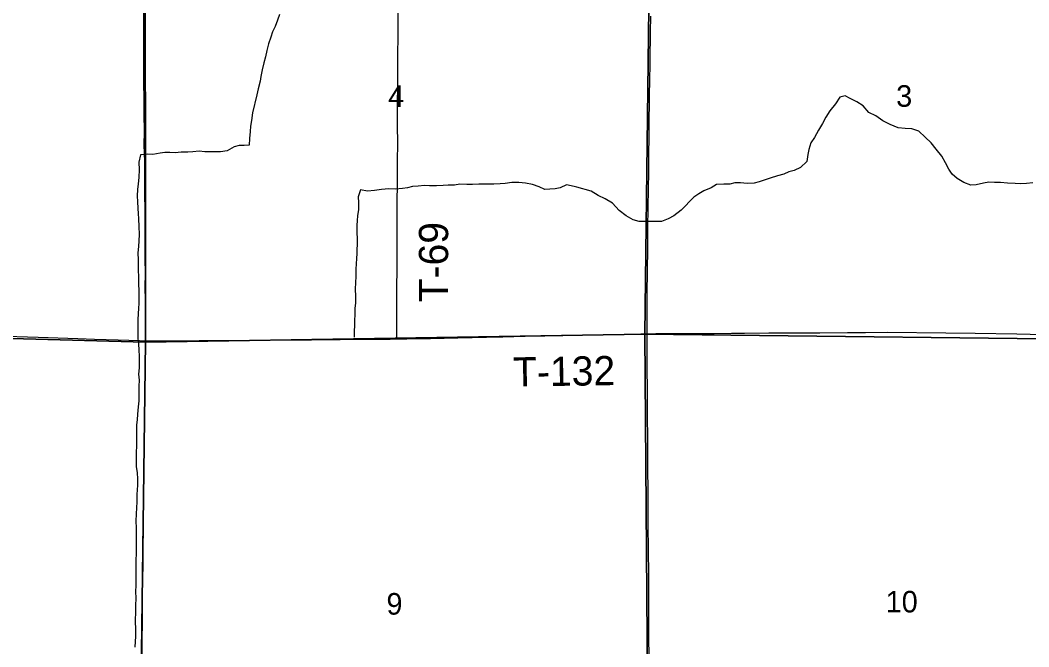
# Model space of a CAD drawing. Extents: x 0 to 34, y 0 to 22.
# Drawn here: x 3.372 to 4.352, y 19.621 to 20.23 of the extents above; entities that cross this region are included whole.
import ezdxf

# ---------------------------------------------------------------- set-up
doc = ezdxf.new("R2010")
doc.units = 0
for name, color, linetype in [('GM_X_Minor_River', 7, 'Continuous'), ('GM_X_Section', 7, 'Continuous'), ('GM_X_Section_Text', 7, 'Continuous'), ('GM_X_Township_Road', 7, 'Continuous'), ('GM_X_Township_Road_Text', 7, 'Continuous')]:
    doc.layers.add(name, color=color, linetype=linetype)

msp = doc.modelspace()

# ---------------------------------------------------------------- linework, layer by layer
at = {"layer": 'GM_X_Minor_River'}
for points in [[(3.62379, 20.23523), (3.62188, 20.22974), (3.61957, 20.22349), (3.61709, 20.21838), (3.61555, 20.21326), (3.61325, 20.20682), (3.61171, 20.20038), (3.61035, 20.19432), (3.60881, 20.18845), (3.60689, 20.18163), (3.60591, 20.17518), (3.60514, 20.17044), (3.60302, 20.16324), (3.60186, 20.15737), (3.5978, 20.13975), (3.59664, 20.13235), (3.59585, 20.12667), (3.59526, 20.12155), (3.59466, 20.11472), (3.59445, 20.10846), (3.58952, 20.10792), (3.58478, 20.10794), (3.57985, 20.10683), (3.5732, 20.10287), (3.56657, 20.10196), (3.56069, 20.10198), (3.55595, 20.10182), (3.55122, 20.10184), (3.54591, 20.10243), (3.53966, 20.1019), (3.53492, 20.10154), (3.52829, 20.10157), (3.5226, 20.10084)], [(4.35571, 20.07189), (4.34965, 20.07097), (4.34378, 20.07082), (4.33866, 20.07104), (4.33109, 20.07146), (4.32428, 20.07207), (4.3184, 20.07211), (4.3131, 20.07233), (4.30779, 20.0716), (4.30078, 20.06993), (4.29566, 20.06958), (4.28886, 20.07209), (4.28225, 20.07611), (4.27736, 20.08032), (4.27398, 20.08508), (4.27079, 20.09118), (4.26723, 20.09765), (4.26197, 20.10433), (4.2569, 20.11062), (4.25125, 20.11616), (4.24504, 20.12189), (4.23804, 20.12421), (4.23161, 20.12463), (4.22498, 20.12505), (4.21723, 20.12851), (4.20987, 20.13197), (4.20308, 20.13676), (4.19628, 20.14021), (4.19083, 20.14651), (4.18479, 20.15034), (4.17837, 20.15361), (4.17347, 20.15629), (4.16816, 20.15499), (4.16414, 20.14856), (4.15841, 20.14176), (4.15459, 20.13552), (4.15152, 20.12927), (4.1475, 20.12284), (4.14348, 20.11584), (4.14004, 20.11074), (4.13811, 20.10429), (4.13732, 20.09917), (4.13633, 20.09253), (4.13004, 20.0865), (4.12396, 20.08387), (4.11884, 20.08238), (4.11371, 20.08033), (4.10764, 20.07865), (4.10062, 20.07642), (4.09474, 20.07436), (4.08999, 20.07268), (4.08487, 20.07138), (4.07824, 20.07123), (4.07161, 20.07184), (4.06631, 20.07187), (4.06138, 20.07038), (4.05551, 20.07061), (4.04831, 20.07027), (4.04317, 20.06688), (4.03615, 20.06388), (4.03121, 20.06106), (4.02626, 20.05768), (4.01406, 20.04522), (4.00702, 20.03975), (4.00132, 20.03675), (3.99486, 20.03432), (3.98937, 20.03416), (3.97895, 20.03422), (3.97327, 20.03407), (3.9676, 20.03581), (3.96062, 20.03984), (3.95383, 20.045), (3.94724, 20.05187), (3.94026, 20.05609), (3.93346, 20.05936), (3.92667, 20.06357), (3.91275, 20.06749)], [(3.5226, 20.10084), (3.51749, 20.10124), (3.51256, 20.10108), (3.50782, 20.10072), (3.5008, 20.09923), (3.49531, 20.09964), (3.48887, 20.0991), (3.48732, 20.09171), (3.48767, 20.08431), (3.48726, 20.0773), (3.48647, 20.07047), (3.48607, 20.06573), (3.48566, 20.0589), (3.48602, 20.05378), (3.48637, 20.04676), (3.48673, 20.04201), (3.48689, 20.0367), (3.48724, 20.0293), (3.4874, 20.02171), (3.48718, 20.01526), (3.48678, 20.00976), (3.48637, 20.0037), (3.48653, 19.99687), (3.4867, 19.99174), (3.48668, 19.98681), (3.48684, 19.98036), (3.48681, 19.97372), (3.48716, 19.9667), (3.48733, 19.96196), (3.4873, 19.95494), (3.4869, 19.94963), (3.4865, 19.94489), (3.48629, 19.93882), (3.48626, 19.93294), (3.48621, 19.92042), (3.48675, 19.91549), (3.48711, 19.90922), (3.48765, 19.90353), (3.48763, 19.89822), (3.48741, 19.89215), (3.48701, 19.88589), (3.48755, 19.88001), (3.48734, 19.87413), (3.4873, 19.86465), (3.48709, 19.8599), (3.48668, 19.85403), (3.48589, 19.84701), (3.48568, 19.84151), (3.48509, 19.83677), (3.48487, 19.82861), (3.48503, 19.8216), (3.48501, 19.81647), (3.4846, 19.80946), (3.48457, 19.80358), (3.48473, 19.7958), (3.48546, 19.79048), (3.486, 19.78403), (3.48598, 19.77796), (3.48518, 19.76886), (3.48515, 19.76203), (3.48493, 19.75558), (3.48472, 19.75046), (3.48431, 19.74268), (3.48448, 19.73699), (3.48423, 19.68008), (3.48402, 19.67534), (3.48418, 19.66775), (3.48415, 19.66169), (3.48412, 19.65448), (3.48371, 19.64708), (3.48405, 19.63646), (3.48383, 19.63096), (3.48362, 19.62621), (3.48322, 19.62052)], [(3.91275, 20.06749), (3.91015, 20.06826), (3.90276, 20.06981), (3.8965, 20.067), (3.89176, 20.06607), (3.88645, 20.06553), (3.88152, 20.06536), (3.87604, 20.06785), (3.8696, 20.07016), (3.86279, 20.07133), (3.85654, 20.07212), (3.84953, 20.07196), (3.84308, 20.07123), (3.83834, 20.07069), (3.83209, 20.07053), (3.82489, 20.07056), (3.81769, 20.07041), (3.81143, 20.07006), (3.80575, 20.07027), (3.79912, 20.07031), (3.794, 20.06938), (3.78775, 20.0696), (3.78282, 20.06906), (3.77637, 20.0689), (3.76974, 20.06893), (3.76482, 20.06914), (3.75875, 20.0686), (3.75306, 20.06806), (3.74813, 20.06694), (3.74339, 20.06621), (3.73657, 20.06567), (3.72994, 20.06589), (3.72292, 20.06517), (3.71629, 20.06425), (3.70927, 20.06372), (3.70265, 20.06489), (3.70034, 20.05807), (3.7007, 20.05275), (3.70048, 20.04593), (3.6997, 20.03986), (3.69949, 20.03512), (3.6989, 20.03019), (3.69888, 20.02526), (3.69921, 20.01577), (3.69916, 20.00306), (3.69876, 19.99832), (3.69836, 19.9932), (3.69796, 19.98789), (3.69793, 19.98087), (3.69771, 19.97499), (3.6975, 19.96835), (3.69766, 19.96153), (3.69763, 19.95526), (3.69723, 19.94977), (3.6972, 19.94427), (3.6968, 19.93763), (3.69659, 19.93289), (3.69657, 19.92814), (3.69654, 19.92188)]]:
    msp.add_lwpolyline(points, dxfattribs=at)
at = {"layer": 'GM_X_Section'}
for points in [[(3.00478, 20.41279), (3.49353, 20.40423), (3.4937, 19.91709), (2.99609, 19.93047)], [(3.98457, 20.40037), (3.97869, 19.92465), (3.4937, 19.91709), (3.49353, 20.40423)], [(3.98457, 20.40037), (4.00029, 20.40044), (4.47952, 20.40723), (4.4798, 19.91877), (3.97869, 19.92465)], [(2.99609, 19.93047), (3.4937, 19.91709), (3.4871, 19.41486), (2.98702, 19.42864)], [(3.4937, 19.91709), (3.97869, 19.92465), (3.98263, 19.41835), (3.4871, 19.41486)], [(3.97869, 19.92465), (4.4798, 19.91877), (4.47488, 19.41917), (3.98263, 19.41835)]]:
    msp.add_lwpolyline(points, close=True, dxfattribs=at)
at = {"layer": 'GM_X_Township_Road'}
for points in [[(3.73779, 19.92022), (3.7379, 19.94442), (3.73802, 19.97053), (3.7381, 19.98762), (3.73818, 20.03021), (3.73828, 20.05663), (3.73837, 20.06719), (3.73856, 20.09175), (3.73869, 20.11133), (3.73866, 20.12656), (3.73865, 20.14645), (3.73878, 20.1679), (3.73879, 20.1881), (3.73902, 20.22229), (3.73919, 20.24809), (3.73951, 20.2801), (3.73967, 20.29502), (3.73967, 20.31367), (3.7398, 20.33636), (3.73999, 20.37086), (3.74024, 20.39386), (3.74039, 20.401), (3.74044, 20.40312)], [(3.49376, 19.91843), (3.4938, 19.93011), (3.49367, 19.94824), (3.49355, 19.95873), (3.49354, 19.96896), (3.49358, 19.98517), (3.49354, 19.99627), (3.49337, 20.00741), (3.49349, 20.02107), (3.49332, 20.03102), (3.49323, 20.04516), (3.49306, 20.06112), (3.49306, 20.07797), (3.49297, 20.09237), (3.49247, 20.10853), (3.49259, 20.12156), (3.49234, 20.13879), (3.49238, 20.15207), (3.49221, 20.17058), (3.49203, 20.21577), (3.4921, 20.23884)], [(3.98104, 19.92519), (3.98095, 19.93859), (3.98119, 19.96439), (3.98159, 20.00791), (3.98186, 20.02873), (3.98213, 20.04676), (3.98252, 20.06695), (3.98271, 20.08125), (3.98274, 20.08934), (3.98277, 20.09524), (3.98292, 20.12042), (3.98303, 20.12942), (3.98308, 20.13096), (3.98307, 20.13159), (3.98309, 20.13438), (3.98317, 20.13995), (3.98323, 20.14182), (3.98323, 20.14244), (3.98325, 20.14461), (3.98336, 20.15112), (3.98341, 20.1533), (3.98342, 20.15392), (3.98345, 20.15702), (3.98374, 20.17163), (3.98396, 20.18717), (3.98401, 20.18996), (3.98401, 20.19058), (3.98442, 20.21825), (3.98454, 20.23379)], [(2.99722, 19.93036), (3.00018, 19.93041), (3.01601, 19.92999), (3.03374, 19.92979), (3.05704, 19.92952), (3.06979, 19.92935), (3.08687, 19.92907), (3.12293, 19.92839), (3.14872, 19.92808), (3.177, 19.92762), (3.21274, 19.92709), (3.25375, 19.92626), (3.28637, 19.92527), (3.31588, 19.92429), (3.33141, 19.9237), (3.34788, 19.92322), (3.3895, 19.92184), (3.42802, 19.92046), (3.44417, 19.92), (3.46716, 19.91932), (3.48797, 19.91862), (3.49376, 19.91843)], [(3.73779, 19.92022), (3.74762, 19.92026), (3.77062, 19.92067), (3.79703, 19.92129), (3.825, 19.92187), (3.84085, 19.92222), (3.86262, 19.92266), (3.88155, 19.92312), (3.89927, 19.92348), (3.92506, 19.92405), (3.94681, 19.92449), (3.97504, 19.92512), (3.98104, 19.92519)], [(3.98104, 19.92519), (3.98939, 19.92529), (4.00337, 19.9253), (4.02204, 19.92546), (4.04626, 19.92551), (4.06304, 19.92564), (4.0757, 19.92577), (4.09931, 19.9259), (4.12201, 19.92595), (4.14882, 19.92616), (4.17556, 19.92631), (4.19328, 19.92644), (4.21453, 19.92655), (4.27107, 19.92611), (4.29988, 19.92572), (4.34015, 19.92502), (4.3661, 19.92433), (4.38884, 19.92347), (4.4078, 19.92282), (4.44193, 19.92172), (4.46306, 19.92095), (4.47952, 19.92033)], [(3.98289, 19.59915), (3.98269, 19.64236), (3.9827, 19.67344), (3.98261, 19.68464), (3.98226, 19.72162), (3.98219, 19.73281), (3.98209, 19.74556), (3.98194, 19.77354), (3.98171, 19.79343), (3.98161, 19.82482), (3.98154, 19.8441), (3.98124, 19.87425), (3.98115, 19.88824), (3.98105, 19.92367), (3.98104, 19.92519)], [(3.49031, 19.61421), (3.49051, 19.62942), (3.49067, 19.64348), (3.49079, 19.6559), (3.4909, 19.66594), (3.49086, 19.67511), (3.49102, 19.68526), (3.49131, 19.70291), (3.49147, 19.71446), (3.49175, 19.73835), (3.49227, 19.79921), (3.49283, 19.8342), (3.49311, 19.86188), (3.49339, 19.89214), (3.49355, 19.90464), (3.49376, 19.91843)], [(3.49376, 19.91843), (3.49606, 19.91842), (3.5144, 19.91833), (3.5458, 19.9185), (3.59957, 19.91897), (3.63686, 19.91918), (3.65489, 19.91932), (3.6695, 19.91951), (3.68285, 19.91953), (3.71114, 19.91975), (3.73124, 19.92003), (3.73779, 19.92022)]]:
    msp.add_lwpolyline(points, dxfattribs=at)

# ---------------------------------------------------------------- texts
at = {"layer": 'GM_X_Section_Text'}
for s, height, p in [('3', 0.02093, (4.22299, 20.14566)), ('4', 0.02093, (3.72945, 20.1454)), ('9', 0.02093, (3.72779, 19.65232)), ('10', 0.020928, (4.21279, 19.65441))]:
    msp.add_text(s, height=height, rotation=0.00001, dxfattribs=at).set_placement(p)
at = {"layer": 'GM_X_Township_Road_Text'}
for s, rotation, p in [('T-69', 90, (3.78772, 19.95563)), ('T-132', 0.84357, (3.85096, 19.87382))]:
    msp.add_text(s, height=0.028409, rotation=rotation, dxfattribs=at).set_placement(p)

doc.saveas('drawing.dxf')
